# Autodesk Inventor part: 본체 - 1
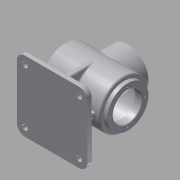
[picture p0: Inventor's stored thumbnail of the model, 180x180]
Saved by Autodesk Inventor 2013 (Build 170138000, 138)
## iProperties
Created: 2015-07
Part Number: 본체 - 1
Material: 알루미늄 6061
Document SubType Name: Modeling
Designer: Administrator
Mass: 1505.64 g
Surface Area: 1284.82 cm^2
Volume: 555.586 cm^3
Density: 2.71 g/cm^3
Author: Administrator
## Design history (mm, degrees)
sketch "스케치1"
  geometry: L1 (-65, 65)-(65, 65); L2 (65, 65)-(65, -65); L3 (65, -65)-(-65, -65); L4 (-65, -65)-(-65, 65); 3 further points
  constraints: 8 end point, 2 midpoint, 2 parallel, 1 horizontal, 1 horizontal alignment, 1 perpendicular, 1 vertical alignment
  dimensions: "d0" = 130 distance of L1.start L1.end; "d2" = 130 distance of L1.end L2.end
extrude "돌출1" new body sketch "스케치1" distance "d3" = 10; taper "d4" = 0 deg
fillet "모깎기1" dims "d5" = 15
sketch "스케치2"
  geometry: C1 r 7.5 at (-50, 50); C2 r 7.5 at (-50, -50); A1 r 15 centre (-50, 50) between (-50, 65) and (-65, 50) reference; A2 r 15 centre (-50, -50) between (-65, -50) and (-50, -65) reference; 1 further point
  constraints: 2 centre point, 2 coincident
  dimensions: "d6" = 15 diameter of C1; "d8" = 15 diameter of C2; "d9" = 100 distance of A2.centre A1.centre (derived)
extrude "돌출2" join sketch "스케치2" distance "d10" = 3; taper "d11" = 0 deg
sketch "스케치3"
  geometry: C1 r 7.5 at (0, 100) reference; C2 r 7.5 at (0, 0) reference; C3 r 5 at (0, 100); C4 r 7.5 at (0, 0) reference; C5 r 5 at (0, 0); 1 further point
  constraints: 2 centre point, 2 coincident
  dimensions: "d12" = 10 diameter of C3; "d14" = 10 diameter of C5
extrude "돌출3" cut sketch "스케치3" stored distance "d15" = 3; taper "d16" = 0 deg
sketch "스케치4"
  geometry: L1 (-50, -65)-(50, -65) reference; L2 (65, -50)-(65, 50) reference; L3 (50, 65)-(-50, 65) reference; L4 (-45, 5)-(-45, -5); L5 (-45, -5)-(45, -5); L6 (-45, 5)-(45, 5); L7 (45, 5)-(45, -5); L8 (-5, 45)-(5, 45); L9 (5, 45)-(5, -45); L10 (5, -45)-(-5, -45); L11 (-5, -45)-(-5, 45); 2 further points
  constraints: 16 end point, 4 perpendicular, 3 parallel, 1 coincident
  dimensions: "d20" = 10 distance of L4.start L4.end; "d23" = 10 distance of L8.start L8.end; "d24" = 10 distance of L9.end L10.end; "d25" = 90 distance of L8.end L9.end; "d26" = 20 distance between parallel lines of L2 L7; "d27" = 60 distance between parallel lines of L2 L9; "d28" = 110 distance between parallel lines of L2 L4; "d29" = 20 distance between parallel lines of L1 L10; "d30" = 70 distance between parallel lines of L1 L6
extrude "돌출4" join sketch "스케치4" distance "d31" = 68; taper "d32" = 0 deg
sketch "스케치5"
  geometry: L1 (0, -65)-(0, 65) reference; L2 (0, 65)-(10, 65) reference; L3 (10, 65)-(10, 45) reference; L4 (10, 45)-(78, 45) reference; L5 (78, 45)-(78, -45) reference; L6 (78, -45)-(10, -45) reference; L7 (10, -45)-(10, -65) reference; L8 (10, -65)-(0, -65) reference; L9 (78, -5)-(78, 5) reference; C1 r 45 at (78, 0); 1 further point
  constraints: 1 centre point, 1 midpoint
  dimensions: "d33" = 90 diameter of C1; "d80" = 78 distance between parallel lines of L1 L5 (derived)
extrude "돌출5" join sketch "스케치5" stored distance "d35" = 110; taper "d36" = 0 deg
node "작업 평면1"
sketch "스케치6"
  geometry: L1 (55, 0)-(-55, 0) reference; C1 r 38 at (0, 0); 1 further point
  constraints: 1 centre point, 1 coincident
  dimensions: "d37" = 76 diameter of C1
extrude "돌출6" join sketch "스케치6" distance "d39" = 30; taper "d40" = 0 deg
sketch "스케치7"
  geometry: C1 r 38 at (0, 0); A1 r 38 centre (0, 0) between (38, 0) and (-38, 0) reference; A2 r 38 centre (0, 0) between (38, 0) and (-38, 0) reference
  constraints: 1 centre point, 1 coincident, 1 concentric
extrude "돌출7" join sketch "스케치7" distance "d41" = 17; taper "d42" = 0 deg
sketch "스케치9"
  geometry: C1 r 38 at (0, 0) reference; C2 r 27 at (0, 0); C3 r 38 at (0, 0) reference
  constraints: 1 centre point, 1 coincident
  dimensions: "d43" = 54 diameter of C2
extrude "돌출8" cut sketch "스케치9" distance "d45" = 60; taper "d46" = 0 deg
sketch "스케치10" dims "d47" = 64
  geometry: L1 (0, 0)-(0, 81.64); C1 r 38 at (0, 0) reference; 1 further point
  constraints: 2 end point, 1 coincident, 1 point on line, 1 vertical, 1 vertical alignment, 2 other
hole "구멍1" sketch "스케치10" at (0, 32) diameter "d49" = 3.242; stored, may be unused: countersink angle "d53" = 90 deg, drill point angle "d55" = 118 deg; dims "d50" = 8, "d51" = 4, "d52" = 2, "d54" = 10
sketch "스케치11"
  geometry: C1 r 45 at (0, 0) reference; C2 r 38 at (0, 0); 1 further point
  constraints: 1 centre point, 1 coincident
  dimensions: "d59" = 76 diameter of C2
extrude "돌출9" join sketch "스케치11" distance "d61" = 7; taper "d62" = 0 deg
sketch "스케치12"
  geometry: C1 r 38 at (0, 0) reference; C2 r 27 at (0, 0); 1 further point
  constraints: 1 centre point, 1 coincident
  dimensions: "d63" = 54 diameter of C2
extrude "돌출10" cut sketch "스케치12" distance "d65" = 30; taper "d66" = 0 deg
sketch "스케치13" dims "d67" = 64
  geometry: L1 (0, 0)-(0, 78.866); C1 r 38 at (0, 0) reference; 2 further points
  constraints: 2 end point, 1 coincident, 1 point on line, 1 vertical, 1 vertical alignment, 2 other
hole "구멍2" sketch "스케치13" at (0, 32) diameter "d69" = 3.242; stored, may be unused: countersink angle "d73" = 90 deg, drill point angle "d75" = 118 deg; dims "d70" = 8, "d71" = 4, "d72" = 2, "d74" = 10
fillet "모깎기3" dims "d82" = 3
fillet "모깎기4" dims "d83" = 3
fillet "모깎기5" dims "d84" = 3
sketch "스케치15"
  geometry: L1 (140, 27)-(80, 27) reference; L2 (80, 27)-(80, -27) reference; L3 (80, -27)-(140, -27) reference; L4 (140, -27)-(140, -30.379) reference; L5 (140, -30.379)-(130, -30.379) reference; L6 (130, -30.379)-(129.026, -32) reference; L7 (129.026, -32)-(130, -33.621) reference; L8 (130, -33.621)-(140, -33.621) reference; L9 (140, -33.621)-(140, -38) reference; L10 (102.96, 38)-(140, 38) reference; L11 (78, -45)-(10, -45) reference; L12 (10, -65)-(0, -65) reference; L13 (0, -65)-(0, 65) reference; L14 (0, 65)-(10, 65) reference; L15 (10, 45)-(78, 45) reference; L16 (140, -38)-(102.96, -38) reference; L17 (140, 38)-(140, 33.621) reference; L18 (140, 33.621)-(130, 33.621) reference; L19 (130, 33.621)-(129.026, 32) reference; L20 (129.026, 32)-(130, 30.379) reference; L21 (130, 30.379)-(140, 30.379) reference; L22 (140, 30.379)-(140, 27) reference; L23 (10, 65)-(10, 45) reference; L24 (10, -45)-(10, -65) reference; C1 r 40 at (78, 0); A1 r 45 centre (78, 0) between (101.4, 38.438) and (78, 45) reference; A2 r 45 centre (78, 0) between (78, -45) and (101.4, -38.437) reference; 1 further point
  constraints: 1 centre point, 1 coincident, 2 other
  dimensions: "d85" = 80 diameter of C1
extrude "돌출11" cut sketch "스케치15" stored distance "d87" = 96; taper "d88" = 0 deg
fillet "모깎기6" dims "d89" = 3
chamfer "모따기1" distance "d90" = 1; stored, may be unused: second distance "d91" = 2, angle "d92" = 45 deg
fillet "모깎기7" dims "d93" = 3
chamfer "모따기2" distance "d94" = 1; stored, may be unused: second distance "d95" = 2, angle "d96" = 45 deg
sketch "스케치16"
  geometry: C1 r 42 at (0, 0) reference; 2 further points
  constraints: 1 coincident, 1 other
extrude "돌출12" join sketch "스케치16" distance "d97" = 0.5; taper "d98" = 0 deg
fillet "모깎기8" dims "d100" = 3
node "솔리드1"
mirror "대칭1"
pattern_circular "원형 패턴1" dims angle "d57" = 360 deg
pattern_circular "원형 패턴2" dims angle "d77" = 360 deg
node "절단 모서리 투영1"
node "절단 모서리 투영2"
node "절단 모서리 투영3"
node "절단 모서리 투영4"
node "절단 모서리 투영6"
